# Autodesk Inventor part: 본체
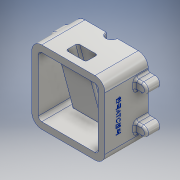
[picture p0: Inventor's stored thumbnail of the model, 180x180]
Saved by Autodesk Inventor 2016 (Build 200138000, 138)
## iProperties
Created: 2018-01
Part Number: 본체
Material: 알루미늄 6061
Document SubType Name: Modeling
Designer: 605-03
Density: 2.7 g/cm^3
Appearance: 알루미늄 - 평지
Mass: 995.217 g
Surface Area: 834.406 cm^2
Volume: 368.599 cm^3
Author: 605-03
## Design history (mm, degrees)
sketch "스케치2"
  geometry: L1 (40, 55)-(-40, 55); L2 (-55, 40)-(-55, -40); L3 (-40, -55)-(40, -55); L4 (55, -40)-(55, 40); L5 (55, 55)-(-55, -55); L6 (-55, 55)-(55, -55); L7 (40, -45)-(-40, -45); L8 (-45, -40)-(-45, 40); L9 (-40, 45)-(40, 45); L10 (45, 40)-(45, -40); A1 r 5 centre (40, -40) between (40, -45) and (45, -40); A2 r 5 centre (40, 40) between (45, 40) and (40, 45); A3 r 5 centre (-40, 40) between (-40, 45) and (-45, 40); A4 r 5 centre (-40, -40) between (-45, -40) and (-40, -45); A5 r 15 centre (40, -40) between (40, -55) and (55, -40); A6 r 15 centre (40, 40) between (55, 40) and (40, 55); A7 r 15 centre (-40, 40) between (-40, 55) and (-55, 40); A8 r 15 centre (-40, -40) between (-55, -40) and (-40, -55); 1 further point
  constraints: 20 end point, 16 point on circle, 16 tangent, 8 centre point, 8 point on line, 6 equal radius, 4 parallel, 2 midpoint, 2 perpendicular, 1 horizontal, 3 other
  dimensions: "d0" = 110 distance of L6.end L5.end; "d1" = 110 distance of L5.end L6.start; "d2" = 10 distance between parallel lines of L3 L7; "d3" = 5 radius of A1; "d4" = 15 radius of A5
extrude "돌출1" new body sketch "스케치2" stored distance "d5" = 65; taper "d6" = 0 deg
sketch "스케치3"
  geometry: L1 (-32.5, -45)-(32.5, -45) reference; L2 (32.5, -45)-(32.5, -55) reference; L3 (32.5, -55)-(-32.5, -55) reference; L4 (-32.5, -55)-(-32.5, -45) reference; L5 (32.5, 45)-(-32.5, 45) reference; L6 (-32.5, 45)-(-32.5, 55) reference; L7 (-32.5, 55)-(32.5, 55) reference; L8 (32.5, 55)-(32.5, 45) reference; L9 (-32.5, -45)-(32.5, -45) reference; L10 (-32.5, 40)-(32.5, 40) reference; L11 (-32.5, -40)-(-32.5, 40) reference; L12 (32.5, -40)-(-32.5, -40) reference; L13 (32.5, 40)-(32.5, -40) reference; L14 (32.5, -40)-(-32.5, -40) reference; L15 (-32.5, -45)-(-32.5, -40) reference; L16 (-32.5, -45)-(32.5, -45) reference; L17 (32.5, -40)-(32.5, -45) reference; L18 (32.5, -40)-(32.5, 40) reference; L19 (32.5, -35)-(-2.5, -35); L20 (-2.5, -35)-(-23.936, 45); L21 (-32.5, 45)-(32.5, 45) reference; L22 (-23.936, 45)-(32.5, 45); L23 (32.5, 45)-(32.5, -35); 1 further point
  constraints: 8 end point, 2 collinear, 2 point on line, 1 horizontal
  dimensions: "d7" = 105 deg angle of L19 L20; "d8" = 20 distance between parallel lines of L3 L19; "d9" = 30 distance from line of L11 L19.end
extrude "돌출2" join sketch "스케치3" stored distance "d10" = 50; taper "d11" = 0 deg
sketch "스케치4"
  geometry: L1 (32.5, -35)-(-2.5, -35) reference; L2 (-2.5, -35)-(-23.936, 45) reference; L3 (-23.936, 45)-(-32.5, 45) reference; L4 (-32.5, 45)-(-32.5, 55) reference; L5 (-32.5, 55)-(32.5, 55) reference; L6 (32.5, 55)-(32.5, -35) reference; L7 (-32.5, -45)-(32.5, -45) reference; L8 (32.5, -45)-(32.5, -55) reference; L9 (32.5, -55)-(-32.5, -55) reference; L10 (-32.5, -55)-(-32.5, -45) reference; L11 (-32.5, 55)-(32.5, 55) reference; L12 (25, 55)-(25, 36); L13 (25, 36)-(17.5, 36); L14 (16.5, 35)-(16.5, 22); L15 (16.5, 22)-(13.5, 22); L16 (12.5, 21)-(12.5, -24); L17 (13.5, -25)-(17.5, -25); L18 (17.5, -25)-(17.5, -29); L19 (18.5, -30)-(32.5, -30); L20 (25, 55)-(32.5, 55); L21 (32.5, -35)-(-2.5, -35) reference; L22 (-2.5, -35)-(-23.936, 45) reference; L23 (-23.936, 45)-(-32.5, 45) reference; L24 (-32.5, 45)-(-32.5, 55) reference; L25 (-32.5, 55)-(32.5, 55) reference; L26 (32.5, 55)-(32.5, -35) reference; L27 (-32.5, -45)-(32.5, -45) reference; L28 (32.5, -45)-(32.5, -55) reference; L29 (32.5, -55)-(-32.5, -55) reference; L30 (-32.5, -55)-(-32.5, -45) reference; L31 (32.5, 45)-(-23.936, 45) reference; L32 (32.5, 45)-(32.5, -35) reference; L33 (32.5, -35)-(-2.5, -35) reference; L34 (-2.5, -35)-(-23.936, 45) reference; L35 (32.5, 55)-(32.5, -30); A1 r 1 centre (17.5, 35) between (17.5, 36) and (16.5, 35); A2 r 1 centre (13.5, 21) between (13.5, 22) and (12.5, 21); A3 r 1 centre (13.5, -24) between (12.5, -24) and (13.5, -25); A4 r 1 centre (18.5, -29) between (17.5, -29) and (18.5, -30); 5 further points
  constraints: 20 end point, 9 point on line, 8 point on circle, 8 tangent, 7 perpendicular, 4 centre point, 3 equal radius, 2 horizontal, 1 collinear
  dimensions: "d12" = 15 diameter of L12 L35; "d13" = 32 diameter of L14 L35; "d14" = 40 diameter of L16 L35; "d15" = 30 diameter of L18 L35; "d16" = 19 distance of L12.start L12.end; "d17" = 14 distance of point (16.5, 36) L14.end; "d18" = 47 distance of point (12.5, 22) point (12.5, -25); "d19" = 5 distance of L17.end point (17.5, -30); "d20" = 1 radius of A1
revolve "회전1" sketch "스케치4" stored, may be unused: angle "d21" = 90 deg
sketch "스케치5"
  geometry: L1 (25, 55)-(25, 36) reference; L2 (25, 36)-(17.5, 36) reference; L3 (16.5, 35)-(16.5, 22) reference; L4 (16.5, 22)-(13.5, 22) reference; L5 (12.5, 21)-(12.5, -24) reference; L6 (13.5, -25)-(17.5, -25) reference; L7 (17.5, -25)-(17.5, -29) reference; L8 (18.5, -30)-(32.5, -30) reference; L9 (32.5, -30)-(32.5, -35) reference; L10 (32.5, -35)-(-2.5, -35) reference; L11 (-2.5, -35)-(-23.936, 45) reference; L12 (-23.936, 45)-(-32.5, 45) reference; L13 (-32.5, 45)-(-32.5, 55) reference; L14 (-32.5, 55)-(25, 55) reference; L15 (32.5, -45)-(32.5, -55) reference; L16 (32.5, -55)-(-32.5, -55) reference; L17 (-32.5, -55)-(-32.5, -45) reference; L18 (-32.5, -45)-(32.5, -45) reference; L19 (-32.5, 55)-(32.5, 55) reference; L20 (-21.439, 55)-(-1.343, -20); L21 (-3.439, 55)-(6.743, 17); L22 (20.306, -20)-(-1.343, -20); L23 (20.306, 17)-(6.743, 17); L24 (-32.5, -40)-(-32.5, 40) reference; L25 (25, 55)-(25, 36) reference; L26 (25, 36)-(17.5, 36) reference; L27 (16.5, 35)-(16.5, 22) reference; L28 (16.5, 22)-(13.5, 22) reference; L29 (12.5, 21)-(12.5, -24) reference; L30 (13.5, -25)-(17.5, -25) reference; L31 (17.5, -25)-(17.5, -29) reference; L32 (18.5, -30)-(32.5, -30) reference; L33 (32.5, -30)-(32.5, -35) reference; L34 (32.5, -35)-(-2.5, -35) reference; L35 (-2.5, -35)-(-23.936, 45) reference; L36 (-23.936, 45)-(-32.5, 45) reference; L37 (-32.5, 45)-(-32.5, 55) reference; L38 (-32.5, 55)-(25, 55) reference; L39 (32.5, -45)-(32.5, -55) reference; L40 (32.5, -55)-(-32.5, -55) reference; L41 (-32.5, -55)-(-32.5, -45) reference; L42 (-32.5, -45)-(32.5, -45) reference; L43 (32.5, 21)-(32.5, -24) reference; L44 (32.5, 21)-(32.5, 21) reference; L45 (32.5, -24)-(32.5, 21) reference; L46 (32.5, -24)-(32.5, -24) reference; L47 (20.306, 17)-(20.306, -20); A1 r 1 centre (17.5, 35) between (17.5, 36) and (16.5, 35) reference; A2 r 1 centre (13.5, 21) between (13.5, 22) and (12.5, 21) reference; A3 r 1 centre (13.5, -24) between (12.5, -24) and (13.5, -25) reference; A4 r 1 centre (18.5, -29) between (17.5, -29) and (18.5, -30) reference; A5 r 6 centre (18.5, -29) between (12.572, -29.928) and (12.584, -30); A6 r 1 centre (17.5, 35) between (17.5, 36) and (16.5, 35) reference; A7 r 1 centre (13.5, 21) between (13.5, 22) and (12.5, 21) reference; A8 r 1 centre (13.5, -24) between (12.5, -24) and (13.5, -25) reference; A9 r 1 centre (18.5, -29) between (17.5, -29) and (18.5, -30) reference; 1 further point
  constraints: 10 end point, 2 horizontal, 2 point on circle, 2 point on line, 1 centre point, 1 perpendicular
  dimensions: "d24" = 5 distance between parallel lines of L11 L20 (derived); "d25" = 75 deg angle of L19 L21; "d26" = 18 distance of L20.start L21.start; "d27" = 37 distance between parallel lines of L22 L23; "d29" = 5 distance between parallel lines of L22 L6; "d31" = 11.06095 distance of L13.end L20.start
extrude "돌출3" cut sketch "스케치5" stored distance "d32" = 30; taper "d33" = 0 deg
sketch "스케치6"
  geometry: L1 (-45, 40)-(-45, -40) reference; L2 (-40, -45)-(-25, -45) reference; L3 (-25, -45)-(-25, 35) reference; L4 (-25, 35)-(25, 35) reference; L5 (25, 35)-(25, -45) reference; L6 (25, -45)-(40, -45) reference; L7 (45, -40)-(45, 40) reference; L8 (40, 45)-(-40, 45) reference; L9 (-40, 55)-(40, 55) reference; L10 (55, 40)-(55, -40) reference; L11 (40, -55)-(7.5, -55) reference; L12 (7.5, -55)-(7.5, -36) reference; L13 (7.5, -36)-(15, -36) reference; L14 (16, -35)-(16, -22) reference; L15 (16, -22)-(19, -22) reference; L16 (20, -21)-(20, 24) reference; L17 (19, 25)-(15, 25) reference; L18 (15, 25)-(15, 29) reference; L19 (14, 30)-(-14, 30) reference; L20 (-15, 29)-(-15, 25) reference; L21 (-15, 25)-(-19, 25) reference; L22 (-20, 24)-(-20, -21) reference; L23 (-19, -22)-(-16, -22) reference; L24 (-16, -22)-(-16, -35) reference; L25 (-15, -36)-(-7.5, -36) reference; L26 (-7.5, -36)-(-7.5, -55) reference; L27 (-7.5, -55)-(-40, -55) reference; L28 (-55, -40)-(-55, 40) reference; L29 (-65, -20.5)-(-55, -20.5); L30 (-65, -35.5)-(-55, -35.5); L31 (-65, 35.5)-(-55, 35.5); L32 (-65, 20.5)-(-55, 20.5); L33 (55, -20.5)-(65, -20.5); L34 (55, -35.5)-(65, -35.5); L35 (55, 20.5)-(65, 20.5); L36 (55, 35.5)-(65, 35.5); L37 (-55, -35.5)-(-55, -20.5); L38 (-55, 20.5)-(-55, 35.5); L39 (55, 20.5)-(55, 35.5); L40 (55, -35.5)-(55, -20.5); L41 (55, -40)-(55, 40) reference; A1 r 5 centre (-40, 40) between (-40, 45) and (-45, 40) reference; A2 r 5 centre (-40, -40) between (-45, -40) and (-40, -45) reference; A3 r 5 centre (40, -40) between (40, -45) and (45, -40) reference; A4 r 5 centre (40, 40) between (45, 40) and (40, 45) reference; A5 r 15 centre (-40, 40) between (-40, 55) and (-55, 40) reference; A6 r 15 centre (40, 40) between (55, 40) and (40, 55) reference; A7 r 15 centre (40, -40) between (40, -55) and (55, -40) reference; A8 r 1 centre (15, -35) between (15, -36) and (16, -35) reference; A9 r 1 centre (19, -21) between (19, -22) and (20, -21) reference; A10 r 1 centre (19, 24) between (20, 24) and (19, 25) reference; A11 r 1 centre (14, 29) between (15, 29) and (14, 30) reference; A12 r 1 centre (-14, 29) between (-14, 30) and (-15, 29) reference; A13 r 1 centre (-19, 24) between (-19, 25) and (-20, 24) reference; A14 r 1 centre (-19, -21) between (-20, -21) and (-19, -22) reference; A15 r 1 centre (-15, -35) between (-16, -35) and (-15, -36) reference; A16 r 15 centre (-40, -40) between (-55, -40) and (-40, -55) reference; A17 r 7.5 centre (-65, -28) between (-65, -20.5) and (-65, -35.5); A18 r 7.5 centre (-65, 28) between (-65, 35.5) and (-65, 20.5); A19 r 7.5 centre (65, -28) between (65, -35.5) and (65, -20.5); A20 r 7.5 centre (65, 28) between (65, 20.5) and (65, 35.5); 1 further point
  constraints: 24 end point, 8 horizontal, 8 point on circle, 8 point on line, 8 tangent, 4 centre point, 4 collinear
  dimensions: "d34" = 15 diameter of A17; "d35" = 27 distance from line of L27 A17.centre; "d36" = 10 distance from line of A17.centre L28; "d37" = 15 diameter of A18; "d38" = 10 distance from line of L28 A18.centre; "d39" = 27 distance from line of L9 A18.centre; "d40" = 15 diameter of A19; "d41" = 15 diameter of A20; "d42" = 10 distance from line of A19.centre L10; "d43" = 27 distance from line of L11 A19.centre; "d44" = 27 distance from line of L9 A20.centre; "d45" = 10 distance from line of L10 A20.centre
extrude "돌출4" join sketch "스케치6" distance "d46" = 20; taper "d47" = 0 deg
hole "구멍1" diameter "d50" = 3.242; stored, may be unused: countersink angle "d54" = 90 deg, drill point angle "d56" = 118 deg; dims "d51" = 9, "d52" = 4, "d53" = 2, "d55" = 11, "d77" = 10, "d78" = 10
hole "구멍2" diameter "d59" = 3.242; stored, may be unused: countersink angle "d63" = 90 deg, drill point angle "d65" = 118 deg; dims "d60" = 9, "d61" = 4, "d62" = 2, "d64" = 11, "d75" = 10, "d76" = 10
hole "구멍3" diameter "d68" = 3.242; stored, may be unused: countersink angle "d72" = 90 deg, drill point angle "d74" = 118 deg; dims "d69" = 9, "d70" = 4, "d71" = 2, "d73" = 11, "d79" = 10, "d80" = 10
hole "구멍4" diameter "d83" = 3.242; stored, may be unused: countersink angle "d87" = 90 deg, drill point angle "d89" = 118 deg; dims "d81" = 10, "d82" = 10, "d84" = 9, "d85" = 4, "d86" = 2, "d88" = 11
sketch "스케치7"
  geometry: L1 (80, 0)-(0, 0) reference; L2 (-15, 0)-(-15, 65) reference; 2 further points
  constraints: 1 other
  dimensions: "d90" = 20 distance from line of L1 point (40, 20); "d91" = 55 distance from line of L2 point (40, 20)
feature "엠보싱1" sketch "스케치7" dims "d92" = 0.5, "d93" = 0
fillet "모깎기1" dims "d94" = 3
fillet "모깎기2" dims "d95" = 3
chamfer "모따기1" distance "d96" = 1; stored, may be unused: second distance "d97" = 2, angle "d98" = 45 deg
chamfer "모따기2" distance "d99" = 1; stored, may be unused: second distance "d100" = 2, angle "d101" = 45 deg
node "솔리드1"
node "투영된 루프1"
node "투영된 루프2"
node "투영된 루프3"
node "투영된 루프4"
node "절단 모서리 투영1"
node "절단 모서리 투영2"
node "절단 모서리 투영3"
node "절단 모서리 투영4"
node "절단 모서리 투영5"
node "절단 모서리 투영6"
